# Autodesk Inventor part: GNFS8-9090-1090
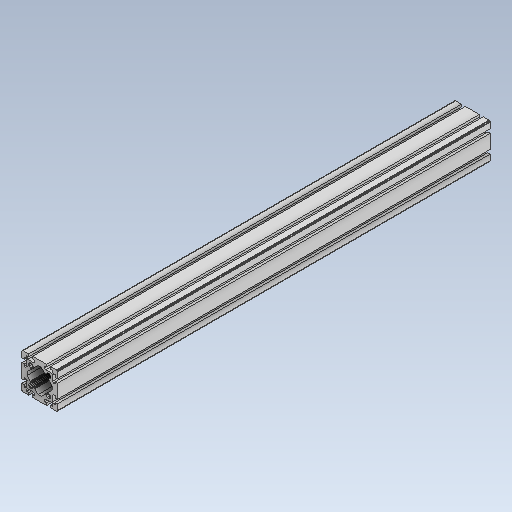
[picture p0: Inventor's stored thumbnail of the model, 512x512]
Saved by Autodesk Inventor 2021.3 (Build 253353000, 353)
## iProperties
Created: 2022-02
Part Number: GNFS8-9090-1090
Material: 一般
Document SubType Name: Modeling
Designer: kengo
Density: 1 g/cm^3
Appearance: 既定
Author: kengo
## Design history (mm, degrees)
feature "GNFS8-9090-1090"
node "ソリッド1"
